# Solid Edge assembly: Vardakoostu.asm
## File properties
Author: Türk
Template: Iso Assembly.asm
Last saved by: Türk
Revision: 5
Application: Solid Edge
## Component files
Vedrustuse varras.par
Poldikoostu3.asm
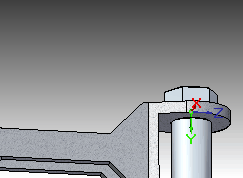
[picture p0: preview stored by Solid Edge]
